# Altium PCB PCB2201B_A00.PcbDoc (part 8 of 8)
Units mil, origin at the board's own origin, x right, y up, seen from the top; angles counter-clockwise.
Board outline 4523.63 x 2358.23 mil, 6 copper layers (Top Layer, Signal Layer 2, Signal Layer 3, Signal Layer 4, Signal Layer 5, Bottom Layer), stack 61.221 mil thick; 383 components, 308 nets, 1386 pads, 1147 vias.
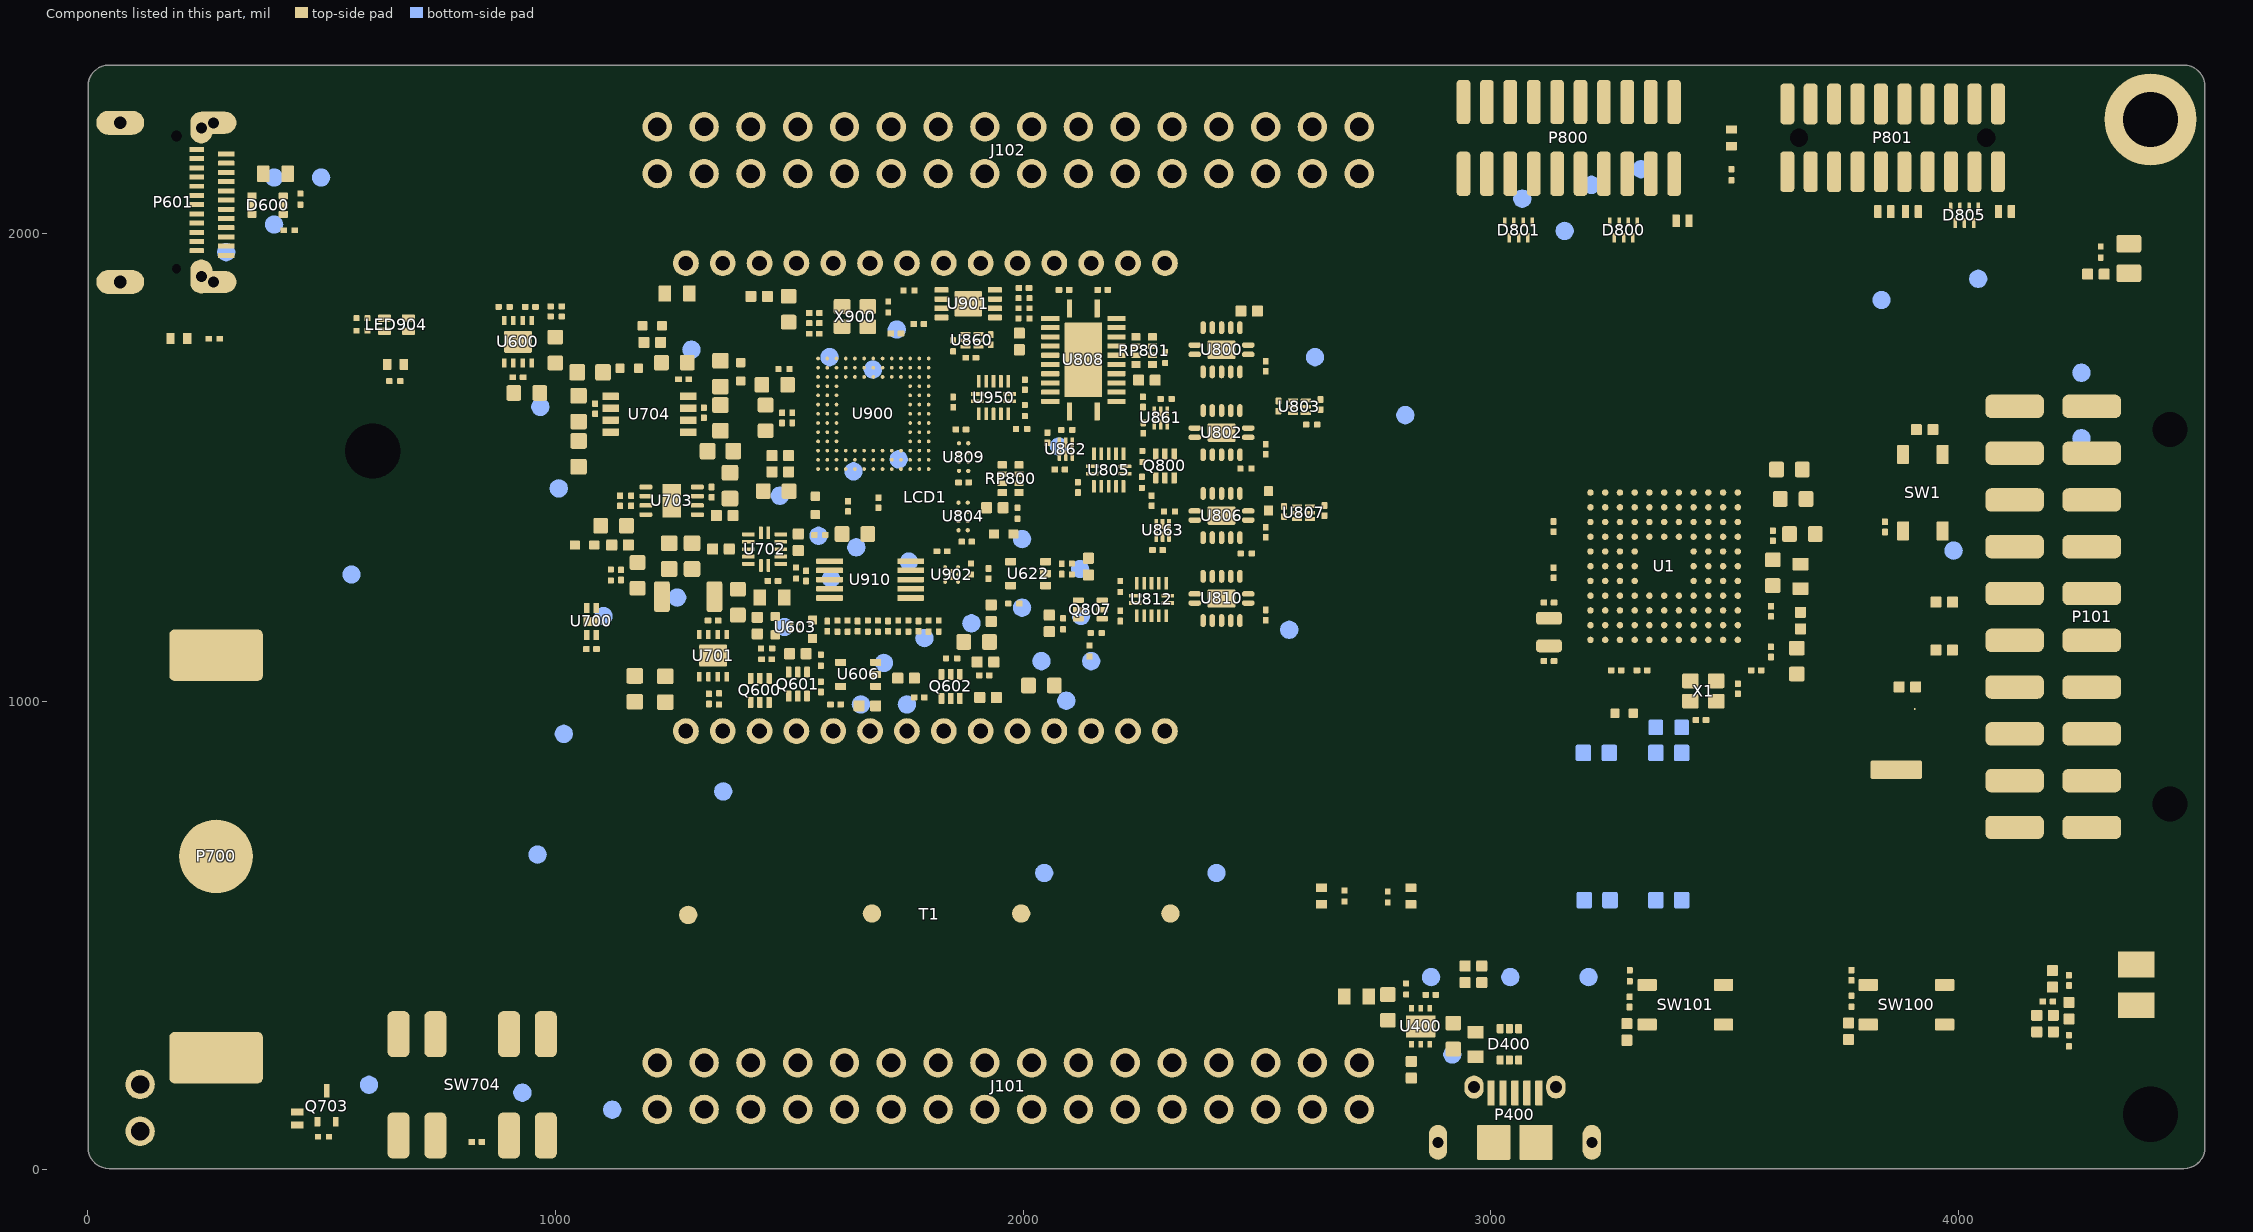
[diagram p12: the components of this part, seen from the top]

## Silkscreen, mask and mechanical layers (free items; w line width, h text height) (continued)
Assembly Drawing Frame:
  lines w7.87: -3599.37,-3547.28 -3599.37,4345.43 7562.05,4345.43 7562.05,-3547.28 -3599.37,-3547.28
